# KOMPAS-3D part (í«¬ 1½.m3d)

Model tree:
1. Эскиз:1
2. Операция выдавливания:1
     Расстояние 1 = 3
3. Эскиз:2
4. Операция выдавливания:2
     Расстояние 1 = 78
5. Эскиз:3
6. Операция выдавливания:3
     Расстояние 1 = 3
7. Эскиз:4
8. Операция выдавливания:4
     Расстояние 1 = 4
9. Эскиз:5
10. Операция выдавливания:5
     Расстояние 1 = 4
11. Эскиз:6
12. Вырезать элемент выдавливания:1
     Расстояние 1 = 18.7
